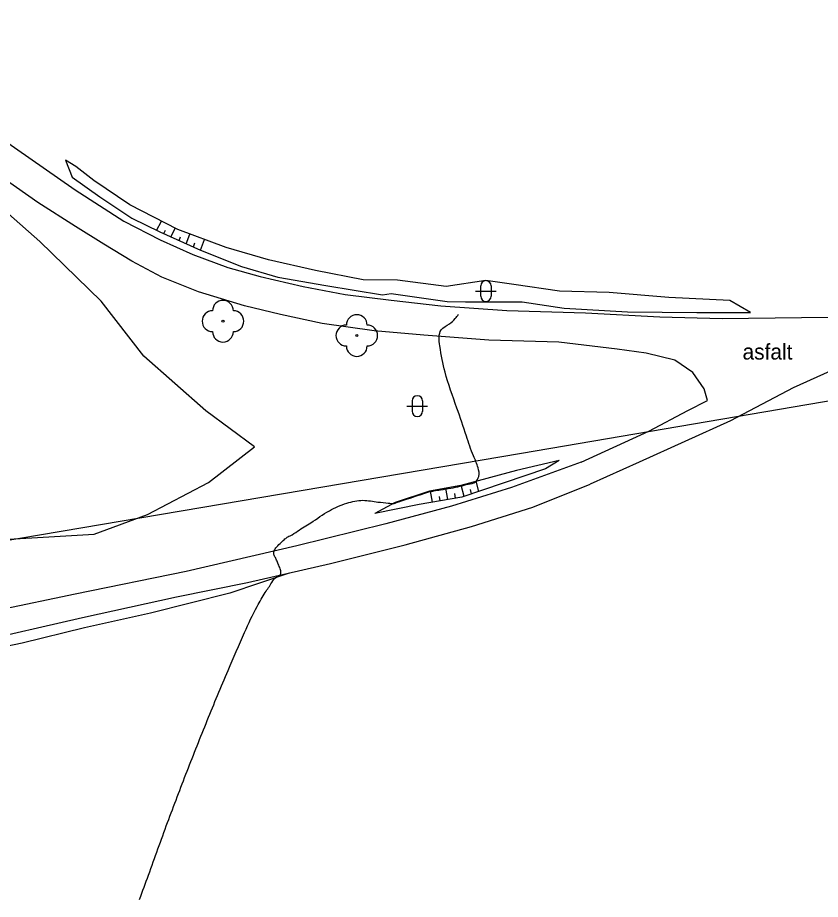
# Model space of a CAD drawing. Extents: x -475575 to -473225, y -1116053 to -1114104.
# Drawn here: x -473610.1 to -473533, y -1115827 to -1115742.4 of the extents above; entities that cross this region are included whole.
import ezdxf

# ---------------------------------------------------------------- set-up
doc = ezdxf.new("R2010")
doc.units = 0
doc.layers.add('Vrstevnice_vedlejsi', color=7, linetype='Continuous')
doc.layers.add('Vrstva_10', color=7, linetype='Continuous')

msp = doc.modelspace()

# ---------------------------------------------------------------- linework, layer by layer
at = {"layer": 'Vrstevnice_vedlejsi'}
msp.add_spline([(-473598.33554471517, -1115827.0394709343), (-473597.4859999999, -1115824.7009999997), (-473595.6589999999, -1115819.6759999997), (-473593.77599999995, -1115814.7269999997), (-473591.83799999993, -1115809.8539999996), (-473589.8439999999, -1115805.0569999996), (-473588.25099999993, -1115801.4099999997), (-473587.05899999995, -1115798.9129999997), (-473586.2689999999, -1115797.5659999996), (-473585.6479999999, -1115796.6289999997), (-473585.1969999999, -1115796.1019999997), (-473584.9159999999, -1115795.9839999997), (-473584.7849999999, -1115795.7559999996), (-473584.8059999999, -1115795.4159999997), (-473584.97799999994, -1115794.9649999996), (-473585.1429999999, -1115794.5669999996), (-473585.3019999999, -1115794.2209999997), (-473585.4549999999, -1115793.9279999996), (-473585.4109999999, -1115793.5869999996), (-473585.1719999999, -1115793.1989999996), (-473584.7369999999, -1115792.7639999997), (-473584.3789999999, -1115792.4419999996), (-473584.09799999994, -1115792.2319999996), (-473583.8929999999, -1115792.1369999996), (-473583.1609999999, -1115791.6869999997), (-473581.90099999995, -1115790.8829999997), (-473580.11299999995, -1115789.7259999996), (-473578.44099999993, -1115789.0079999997), (-473576.88599999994, -1115788.7299999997), (-473575.4479999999, -1115788.8909999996), (-473574.45199999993, -1115788.9869999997), (-473573.8979999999, -1115789.0189999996), (-473573.7849999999, -1115788.9869999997), (-473573.3599999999, -1115788.8479999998), (-473572.6209999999, -1115788.6019999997), (-473571.56999999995, -1115788.2489999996), (-473570.8569999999, -1115788.0119999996), (-473570.4819999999, -1115787.8889999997), (-473570.44499999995, -1115787.8819999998), (-473570.0959999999, -1115787.8239999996), (-473569.4319999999, -1115787.7159999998), (-473568.45599999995, -1115787.5589999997), (-473567.5719999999, -1115787.3789999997), (-473566.7799999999, -1115787.1769999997), (-473566.0799999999, -1115786.9529999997), (-473565.7629999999, -1115786.4269999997), (-473565.8279999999, -1115785.5999999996), (-473566.2749999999, -1115784.4709999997), (-473566.9539999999, -1115782.5639999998), (-473567.86499999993, -1115779.8769999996), (-473569.0069999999, -1115776.4109999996), (-473569.5069999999, -1115773.9069999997), (-473569.36499999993, -1115772.3639999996), (-473568.5799999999, -1115771.7819999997), (-473568.02599999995, -1115771.2819999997), (-473567.7029999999, -1115770.8639999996)], degree=3, dxfattribs=at)
at = {"layer": 'Vrstva_10'}
for p, q in [((-473596.7074513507, -1115762.809227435), (-473596.2509691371, -1115761.9297154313)), ((-473596.02787557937, -1115763.1279540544), (-473595.85084097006, -1115762.7868584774)), ((-473595.3415232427, -1115763.4336241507), (-473594.9196089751, -1115762.6207147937)), ((-473593.8662333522, -1115764.09065113), (-473593.5261426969, -1115763.1713373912)), ((-473594.5527950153, -1115763.7848878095), (-473594.42349816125, -1115763.4353798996)), ((-473593.17967168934, -1115764.3964144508), (-473593.036896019, -1115764.01047137)), ((-473592.49304308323, -1115764.7019968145), (-473592.1193223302, -1115763.691776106)), ((-473565.5854586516, -1115768.1425960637), (-473565.5854586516, -1115769.1425960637)), ((-473564.5854586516, -1115768.1425960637), (-473564.5854586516, -1115769.1425960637)), ((-473566.0854586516, -1115768.6425960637), (-473564.0854586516, -1115768.6425960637)), ((-473572.17414313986, -1115779.1896559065), (-473572.17414313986, -1115780.1896559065)), ((-473571.17414313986, -1115779.1896559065), (-473571.17414313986, -1115780.1896559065)), ((-473572.67414313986, -1115779.6896559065), (-473570.67414313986, -1115779.6896559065)), ((-473565.7535161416, -1115787.8677485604), (-473566.0131063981, -1115786.8974231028)), ((-473568.7290527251, -1115788.658857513), (-473568.93562650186, -1115787.5655102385)), ((-473567.1766428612, -1115788.3522737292), (-473567.4621472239, -1115787.285083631)), ((-473566.4650795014, -1115788.1100111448), (-473566.5740984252, -1115787.7025080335)), ((-473570.20721705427, -1115788.9148889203), (-473570.409549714, -1115787.8439888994)), ((-473569.4681348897, -1115788.7868732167), (-473569.549916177, -1115788.3540237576)), ((-473567.9899705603, -1115788.5308418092), (-473568.0734482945, -1115788.0890134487))]:
    msp.add_line(p, q, dxfattribs=at)
for points in [[(-473632.25499999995, -1115740.9309999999), (-473624.9359999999, -1115745.2259999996), (-473618.17499999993, -1115749.3249999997), (-473611.7689999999, -1115753.8989999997), (-473604.53799999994, -1115758.9199999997), (-473599.85799999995, -1115761.9369999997), (-473596.3599999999, -1115763.7119999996), (-473593.2149999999, -1115765.1189999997), (-473589.8559999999, -1115766.3739999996), (-473586.7679999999, -1115767.2519999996), (-473582.6229999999, -1115768.1929999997), (-473578.59699999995, -1115768.971), (-473574.17499999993, -1115769.5209999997), (-473569.3939999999, -1115770.0599999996), (-473563.0669999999, -1115770.5109999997), (-473555.5289999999, -1115770.7339999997), (-473548.3709999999, -1115771.103), (-473542.3769999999, -1115771.265), (-473534.77699999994, -1115771.1869999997), (-473525.16199999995, -1115771.0889999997)], [(-473555.93399999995, -1115785.0519999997), (-473549.41899999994, -1115782.0849999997), (-473545.6929999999, -1115780.1119999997), (-473543.78899999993, -1115779.1329999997), (-473544.1159999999, -1115778.0129999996), (-473545.2079999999, -1115776.4699999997), (-473546.9439999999, -1115775.282), (-473549.6919999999, -1115774.5899999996), (-473552.47799999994, -1115774.2019999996), (-473558.06599999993, -1115773.5329999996), (-473564.7849999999, -1115773.346), (-473571.04299999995, -1115772.8789999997), (-473575.8069999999, -1115772.471), (-473580.7949999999, -1115771.7669999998), (-473584.79899999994, -1115770.8919999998), (-473588.26599999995, -1115770.0709999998), (-473592.6719999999, -1115768.711), (-473596.22199999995, -1115767.2959999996), (-473599.09299999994, -1115765.7639999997), (-473601.76499999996, -1115764.1349999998), (-473604.4849999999, -1115762.4519999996), (-473608.1009999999, -1115760.123), (-473613.76099999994, -1115756.1949999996)], [(-473605.47199999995, -1115756.0569999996), (-473604.80299999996, -1115757.6969999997), (-473602.16799999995, -1115759.5979999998), (-473599.07499999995, -1115761.6289999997), (-473596.4049999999, -1115762.9599999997), (-473592.4979999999, -1115764.6999999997), (-473588.5459999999, -1115766.292), (-473585.0779999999, -1115767.2909999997), (-473580.43999999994, -1115768.1119999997), (-473575.0129999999, -1115769.0089999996), (-473574.18999999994, -1115768.8809999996), (-473568.8019999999, -1115769.6269999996), (-473567.0349999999, -1115769.6639999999), (-473561.5849999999, -1115769.6749999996), (-473557.5739999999, -1115770.2709999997), (-473551.4919999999, -1115770.6349999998), (-473544.82099999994, -1115770.7079999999), (-473539.66799999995, -1115770.6879999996)], [(-473539.66799999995, -1115770.6879999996), (-473541.6659999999, -1115769.5519999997), (-473547.5239999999, -1115769.2719999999), (-473553.22899999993, -1115768.7869999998), (-473558.0029999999, -1115768.6379999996), (-473562.3989999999, -1115767.9999999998), (-473565.0779999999, -1115767.6199999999), (-473568.8839999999, -1115768.2049999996), (-473573.5609999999, -1115767.6019999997), (-473576.8769999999, -1115767.569), (-473581.44099999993, -1115766.6689999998), (-473585.9479999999, -1115765.6509999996), (-473590.0399999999, -1115764.461), (-473594.68399999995, -1115762.7429999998), (-473599.2849999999, -1115760.3549999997), (-473602.73399999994, -1115758.0339999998), (-473604.45699999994, -1115756.6779999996), (-473605.47199999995, -1115756.0569999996)], [(-473616.57499999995, -1115792.7789999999), (-473608.1539999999, -1115792.3069999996), (-473602.7099999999, -1115791.9789999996), (-473597.57699999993, -1115790.1009999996), (-473591.7249999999, -1115787.0339999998), (-473587.2919999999, -1115783.596), (-473591.98999999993, -1115780.1389999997), (-473597.92799999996, -1115774.8789999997), (-473602.0179999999, -1115769.6119999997), (-473607.91299999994, -1115763.8809999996), (-473613.9909999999, -1115758.5729999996)], [(-473501.14099999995, -1115773.4739999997), (-473509.3179999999, -1115773.6159999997), (-473518.20199999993, -1115773.7499999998), (-473526.08599999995, -1115774.3849999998), (-473530.3779999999, -1115775.6009999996), (-473535.5629999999, -1115777.9289999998), (-473541.5999999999, -1115781.1119999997), (-473550.34799999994, -1115785.0819999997), (-473555.0605095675, -1115787.1685775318)], [(-473506.6719999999, -1115774.8419999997), (-473561.6649999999, -1115784.2399999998), (-473617.4199999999, -1115793.6729999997), (-473672.8719999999, -1115803.157), (-473728.4089999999, -1115812.9229999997), (-473782.8769999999, -1115820.7309999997)], [(-473555.93399999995, -1115785.0519999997), (-473562.6179999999, -1115787.4929999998), (-473568.37399999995, -1115789.2829999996), (-473574.6819999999, -1115790.9949999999), (-473583.24399999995, -1115793.0829999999), (-473593.8679999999, -1115795.5609999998), (-473604.52099999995, -1115797.7449999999), (-473611.89599999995, -1115799.2609999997), (-473620.70099999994, -1115801.211), (-473630.2859999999, -1115803.4969999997), (-473638.5029999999, -1115805.2959999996), (-473650.7299999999, -1115807.4409999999), (-473659.86999999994, -1115808.9699999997), (-473669.50099999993, -1115810.5029999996), (-473678.23999999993, -1115811.6529999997), (-473685.3289999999, -1115812.6369999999), (-473689.4639999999, -1115813.6479999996), (-473696.62499999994, -1115815.8069999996), (-473705.72199999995, -1115818.211), (-473715.1339999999, -1115821.1709999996)], [(-473558.05499999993, -1115784.8959999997), (-473562.1539999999, -1115785.8649999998), (-473567.48799999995, -1115787.292), (-473570.48899999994, -1115787.8589999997), (-473573.8079999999, -1115788.9429999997), (-473575.7569999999, -1115789.9919999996)], [(-473558.05499999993, -1115784.8959999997), (-473559.36299999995, -1115785.6919999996), (-473567.40199999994, -1115788.4289999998), (-473571.47799999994, -1115789.1349999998), (-473575.7569999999, -1115789.9919999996)], [(-473709.8829999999, -1115821.9649999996), (-473702.34799999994, -1115819.7439999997), (-473695.34199999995, -1115817.6619999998), (-473687.9429999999, -1115815.7229999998), (-473683.92299999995, -1115814.7869999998), (-473679.37399999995, -1115814.1639999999), (-473672.61899999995, -1115813.5309999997), (-473663.63499999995, -1115812.1069999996), (-473653.7199999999, -1115810.6159999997), (-473646.3789999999, -1115809.2739999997), (-473639.53199999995, -1115807.8039999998), (-473631.9489999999, -1115806.3079999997), (-473623.88499999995, -1115804.5599999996), (-473614.4699999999, -1115802.4099999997), (-473603.8219999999, -1115799.9889999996), (-473594.80399999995, -1115798.0039999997), (-473587.9689999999, -1115796.6319999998), (-473580.00499999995, -1115794.8049999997), (-473572.83699999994, -1115793.0159999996), (-473566.4479999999, -1115791.2429999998), (-473560.57599999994, -1115789.3789999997), (-473555.0605095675, -1115787.1685775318)], [(-473583.9869999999, -1115795.7185000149), (-473589.69099999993, -1115797.6329999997), (-473597.29799999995, -1115799.5509999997), (-473603.61899999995, -1115800.9759999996), (-473609.6119999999, -1115802.451), (-473615.8059999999, -1115803.7299999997), (-473622.4209999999, -1115805.1829999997), (-473627.42299999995, -1115806.2869999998), (-473635.27099999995, -1115808.1059999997), (-473642.30499999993, -1115809.4799999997), (-473649.6709999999, -1115810.9519999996), (-473656.4219999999, -1115812.1419999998), (-473661.9259999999, -1115813.0949999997), (-473669.0469999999, -1115813.9059999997), (-473674.0679999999, -1115815.1239999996), (-473676.65199999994, -1115816.3429999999), (-473678.3609999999, -1115817.5189999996), (-473681.1599999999, -1115819.7589999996)]]:
    msp.add_lwpolyline(points, dxfattribs=at)
for centre in [(-473590.3349999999, -1115771.5309999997), (-473577.48299999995, -1115772.9089999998)]:
    msp.add_circle(centre, 0.09999906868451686, dxfattribs=at)
for centre, radius, start, end in [((-473565.0768585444, -1115768.1352007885), 0.49999534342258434, 0, 180), ((-473565.0768585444, -1115769.135191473), 0.49999534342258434, 180, 0), ((-473590.3349999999, -1115770.531009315), 0.9999906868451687, 0, 180), ((-473591.33499068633, -1115771.5309999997), 0.9999906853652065, 90, 270), ((-473589.3350093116, -1115771.5309999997), 0.9999906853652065, 270, 89.99999999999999), ((-473577.48299999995, -1115771.9090093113), 0.9999906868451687, 0, 180), ((-473578.4829906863, -1115772.9089999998), 0.9999906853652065, 90, 270), ((-473576.4830093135, -1115772.9089999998), 0.9999906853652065, 270, 89.99999999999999), ((-473590.3349999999, -1115772.530990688), 0.9999906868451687, 180, 0), ((-473577.48299999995, -1115773.9089906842), 0.9999906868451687, 180, 0), ((-473571.6655430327, -1115779.1822606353), 0.49999534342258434, 0, 180), ((-473571.6655430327, -1115780.1822513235), 0.49999534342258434, 180, 0)]:
    msp.add_arc(centre, radius, start, end, dxfattribs=at)

# ---------------------------------------------------------------- texts
msp.add_text('asfalt', height=1.5, dxfattribs=at).set_placement((-473540.43098095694, -1115775.2125176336))

doc.saveas('drawing.dxf')
